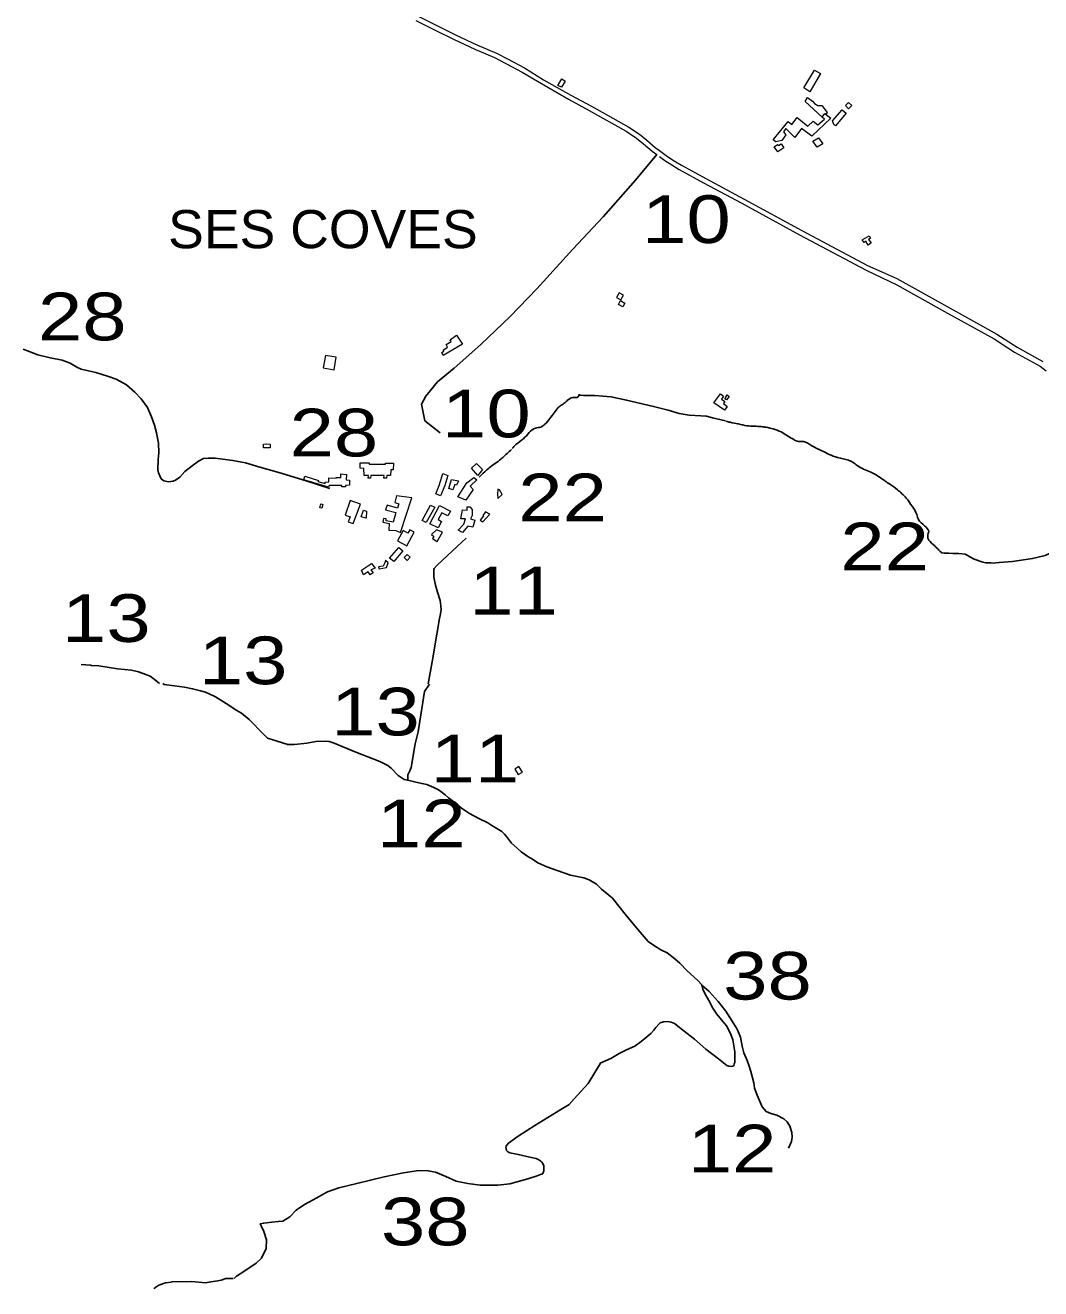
# Model space of a CAD drawing. Extents: x 476989 to 498418, y 4381813 to 4416555.
# Drawn here: x 484535 to 485599, y 4385813 to 4387137 of the extents above; entities that cross this region are included whole.
import ezdxf
from ezdxf.enums import TextEntityAlignment as Align

# ---------------------------------------------------------------- set-up
doc = ezdxf.new("R2010")
doc.units = 0
doc.header["$LTSCALE"] = 20
doc.linetypes.add('MEDIUM_DASHED', pattern=[4.5, 3, -1.5])
for name, color, linetype, lineweight in [('13', 7, 'Continuous', 13), ('36', 7, 'Continuous', 13), ('47', 7, 'Continuous', 13), ('48', 7, 'MEDIUM_DASHED', 13), ('6', 7, 'Continuous', 25)]:
    doc.layers.add(name, color=color, linetype=linetype, lineweight=lineweight)
doc.layers.add('7', color=7, linetype='Continuous')

msp = doc.modelspace()

# ---------------------------------------------------------------- linework, layer by layer
at = {"layer": '36'}
for points in [[(484944.1, 4387141.99), (484964.47, 4387131.61), (484984.32, 4387121.95), (485006.12, 4387111.66), (485026.67, 4387103.08), (485038.55, 4387096.84), (485055.45, 4387087.66), (485071.49, 4387078.37), (485104.22, 4387059.29), (485125.9, 4387047.57), (485164.72, 4387025.8), (485175.49, 4387018.62), (485182.86, 4387012.44), (485191.84, 4387004.83), (485196.68, 4387001.41)], [(484946.46, 4387146.48), (484966.73, 4387136.15), (484986.51, 4387126.53), (485008.19, 4387116.3), (485028.83, 4387107.68), (485040.94, 4387101.32), (485057.93, 4387092.09), (485077.85, 4387079.8), (485106.7, 4387063.72), (485128.35, 4387052.02), (485167.37, 4387030.13), (485178.54, 4387022.69), (485186.13, 4387016.32), (485194.95, 4387008.84), (485199.56, 4387005.59), (485207.95, 4386999.32), (485214.97, 4386994.81), (485222.72, 4386990.21), (485248.09, 4386976.31), (485288.29, 4386954.73), (485348.62, 4386921.76), (485417.64, 4386885.14), (485448.2, 4386871.57)], [(485199.66, 4386999.18), (485205.06, 4386995.15), (485212.3, 4386990.49), (485220.21, 4386985.8), (485245.67, 4386971.85), (485285.88, 4386950.27), (485346.2, 4386917.3), (485416.17, 4386880.07), (485448.2, 4386864.89)], [(485448.2, 4386871.57), (485504.34, 4386840.28), (485553.22, 4386813.06), (485574.47, 4386799.34), (485601.49, 4386784.39)], [(485448.2, 4386864.89), (485501.51, 4386835.18), (485550.21, 4386808.06), (485564.49, 4386798.84)], [(485564.49, 4386798.84), (485571.47, 4386794.33), (485598.37, 4386779.45), (485604.95, 4386774.75)]]:
    msp.add_lwpolyline(points, dxfattribs=at)
at = {"layer": '47'}
for points in [[(485368.22, 4387086.2), (485357.27, 4387067.19), (485350.67, 4387071.13), (485362.11, 4387089.78)], [(485097.24, 4387080.64), (485100.57, 4387078.42), (485096.97, 4387071.84), (485093.08, 4387073.8)], [(485394.39, 4387052.63), (485397.68, 4387049.39), (485401.01, 4387052.87), (485397.7, 4387056.05)], [(485372.99, 4387044.3), (485379, 4387039.44), (485359.12, 4387020.48), (485348.48, 4387028.62), (485341.4, 4387019.09), (485332.09, 4387028.81), (485329.57, 4387025.05), (485331.9, 4387022.2), (485327.68, 4387016.19), (485321.58, 4387014.58), (485318.65, 4387016.84), (485334.49, 4387035.93), (485338.08, 4387032.94), (485343.81, 4387040.06), (485355.18, 4387030.96), (485360.7, 4387036.3), (485365.34, 4387032.5), (485372.61, 4387038.49), (485370.16, 4387040.56)], [(485391.11, 4387048.23), (485395.02, 4387044.71), (485384.02, 4387031.63), (485382.12, 4387032.82), (485380.94, 4387036.71)], [(485327, 4387012.45), (485329.8, 4387008.42), (485323.53, 4387004.21), (485319.77, 4387009.59), (485323.16, 4387012.07), (485324.25, 4387010.89)], [(485366.04, 4387018.89), (485370.57, 4387012.53), (485364.64, 4387009.06), (485360.3, 4387015.36)], [(485414.1, 4386909.21), (485412, 4386912.03), (485419.3, 4386916.24), (485420.78, 4386913.81), (485418.73, 4386912.47), (485421.25, 4386908.69), (485418.22, 4386906.38), (485415.81, 4386910.6)], [(485159.11, 4386849.19), (485161.77, 4386854.02), (485157.33, 4386856.45), (485154.56, 4386851.45)], [(485158.77, 4386848.3), (485163.02, 4386845.74), (485161.19, 4386841.81), (485156.57, 4386844.26)], [(484986.77, 4386812.07), (484993.03, 4386802.65), (484972.62, 4386790.82), (484971.23, 4386794), (484973.4, 4386795.11), (484972.72, 4386796.45), (484977.43, 4386799.32), (484975.89, 4386802.33), (484981.16, 4386805.24), (484980.03, 4386807.2)], [(484849.44, 4386790.77), (484846.94, 4386777.85), (484858.51, 4386775.82), (484860.5, 4386788.91)], [(485267.8, 4386733.43), (485256.48, 4386741.12), (485263.36, 4386750.59), (485266.67, 4386747.96), (485264.52, 4386745.08), (485268.18, 4386742.35), (485266.49, 4386740.36), (485270.62, 4386737.25)], [(485272.72, 4386747.91), (485269.84, 4386744.21), (485268.02, 4386745.4), (485269.25, 4386747.04), (485268.91, 4386747.33), (485270.37, 4386749.54)], [(484791.59, 4386697.69), (484791.41, 4386693.78), (484784.36, 4386694.03), (484784.57, 4386697.72), (484787.22, 4386698.3)], [(484912.38, 4386677.94), (484920.75, 4386677.78), (484920.46, 4386671.05), (484917.81, 4386671.05), (484917.39, 4386664.88), (484913.7, 4386664.88), (484913.51, 4386662.27), (484910.67, 4386662.23), (484910.82, 4386664.83), (484896.88, 4386664.88), (484896.69, 4386662.27), (484894.26, 4386662.29), (484894.38, 4386664.94), (484889.81, 4386664.95), (484889.46, 4386672.4), (484885.79, 4386672.68), (484885.72, 4386678.1), (484888.41, 4386678.06), (484895.26, 4386678.11), (484895.2, 4386676.96), (484912.45, 4386676.68)], [(484874.65, 4386654.69), (484870.48, 4386654.58), (484870.46, 4386653.02), (484866.58, 4386653.01), (484866.49, 4386654.59), (484853.21, 4386654.39), (484852.68, 4386652.83), (484826.61, 4386660.29), (484827.71, 4386664.28), (484842.06, 4386659.71), (484841.42, 4386658.6), (484849.07, 4386656.47), (484849.11, 4386658.07), (484852.95, 4386658.16), (484852.97, 4386662.54), (484860.65, 4386662.23), (484860.59, 4386662.87), (484865.39, 4386662.92), (484865.39, 4386666.55), (484871.56, 4386665.85), (484871.09, 4386660.58), (484874.62, 4386659.92)], [(484965.07, 4386645.88), (484968.64, 4386654.55), (484972.34, 4386666.93), (484977.49, 4386665.02), (484974.53, 4386654.43), (484969.91, 4386643.72)], [(485009.06, 4386664.93), (485002.56, 4386672.56), (485007.64, 4386677.52), (485014.09, 4386671.17)], [(484982.82, 4386649.95), (484978.55, 4386651.27), (484981.38, 4386660.9), (484988.94, 4386659.2), (484986.79, 4386654.97), (484985.12, 4386655.57)], [(484996.43, 4386639.1), (484988.3, 4386642.47), (484997.48, 4386657.34), (485004.88, 4386662.98), (485007.91, 4386660.32), (485001.03, 4386653.8), (485004.26, 4386650.11)], [(484878.58, 4386614.5), (484885.94, 4386635.06), (484875.22, 4386638.61), (484870.18, 4386623.37), (484875.16, 4386621.77), (484873.26, 4386616.47)], [(484928.18, 4386605.08), (484939.97, 4386641.51), (484923.72, 4386643.6), (484923.72, 4386643.6), (484922.15, 4386636.75), (484926.42, 4386635.39), (484924.89, 4386630.56), (484914.1, 4386633.92), (484912.38, 4386628.99), (484923.2, 4386626.01), (484920.36, 4386615.87), (484913.03, 4386617.33), (484913.16, 4386619.43), (484910.06, 4386619.81), (484909.64, 4386615.9), (484916.17, 4386614.67), (484915.69, 4386607.82), (484923.12, 4386607.18)], [(485030.11, 4386650.61), (485029.58, 4386644.86), (485029.99, 4386640.89), (485034.75, 4386645), (485031.79, 4386649.97)], [(484844.5, 4386635.18), (484846.55, 4386634.63), (484845.65, 4386630.54), (484843.47, 4386631)], [(484886.83, 4386621.49), (484889.37, 4386628.45), (484892.44, 4386627.58), (484892, 4386620.32)], [(484963.89, 4386631.61), (484955.07, 4386615.72), (484950.82, 4386617.68), (484959.38, 4386633.93)], [(484967.69, 4386609.95), (484958.91, 4386614.38), (484968.97, 4386633.65), (484980.35, 4386627.47), (484977.58, 4386622.58), (484971.41, 4386625.97), (484967.47, 4386618.74), (484971.14, 4386616.66)], [(484988.42, 4386607.8), (484994.31, 4386613.95), (484996.03, 4386619.44), (484991.42, 4386619.37), (484993.16, 4386629.13), (484997.81, 4386628.54), (484998.06, 4386632.15), (485000.73, 4386632.13), (485003.26, 4386629.33), (485003.18, 4386623.16), (485001.26, 4386619.51), (485005.92, 4386618.3), (485003.83, 4386610.74), (484998.71, 4386611.89), (484992.95, 4386605.26)], [(485011.45, 4386618.18), (485014.46, 4386616.41), (485021.54, 4386624.32), (485017.31, 4386627), (485014.34, 4386623.18), (485015.15, 4386622.6)], [(484930.93, 4386607.22), (484924.86, 4386596.58), (484934.84, 4386591.38), (484942.38, 4386605.69), (484937.68, 4386607.95), (484935.78, 4386604.53)], [(484966.64, 4386595.92), (484972.22, 4386605.45), (484965.86, 4386607.86), (484960.42, 4386603.19), (484963.09, 4386601.11), (484961.54, 4386598.91)], [(484930.53, 4386586.08), (484920.88, 4386574.84), (484916.58, 4386578.14), (484926.15, 4386589.6)], [(484897.59, 4386572.87), (484901.46, 4386567.77), (484897.1, 4386566.06), (484899.31, 4386562.89), (484896.16, 4386560.94), (484894.13, 4386564.12), (484889.43, 4386560.81), (484887.27, 4386565.75)], [(484911.46, 4386573.35), (484909.91, 4386569.85), (484905.06, 4386569.06), (484905.54, 4386567.13), (484913.36, 4386568.57), (484915.04, 4386573.28), (484912.15, 4386575.78)], [(484931.93, 4386579.1), (484935.2, 4386575.97), (484938.33, 4386579.24), (484934.89, 4386582.26)]]:
    msp.add_lwpolyline(points, close=True, dxfattribs=at)
msp.add_lwpolyline([(485370.16, 4387040.56), (485352.1, 4387056.87), (485354.61, 4387061.18), (485359.78, 4387057.35), (485362.15, 4387054.85), (485365.59, 4387052.79), (485369.74, 4387052.73), (485375.25, 4387045.3), (485374.01, 4387043.48)], dxfattribs=at)
at = {"layer": '48'}
msp.add_lwpolyline([(485047.97, 4386357.07), (485051.39, 4386351.42), (485055.76, 4386354.03), (485052.03, 4386360.03)], close=True, dxfattribs=at)
at = {"layer": '6'}
msp.add_line((484669.78, 4386451.55), (484675.59, 4386447), dxfattribs=at)
for points in [[(485196.68, 4387001.41), (485174.53, 4386974.43), (485140.42, 4386936.16), (485108.67, 4386902.09), (485070.95, 4386860.47), (485042.96, 4386831.45), (485012.41, 4386802.17), (484984.19, 4386777.31), (484966.85, 4386762.96), (484954.68, 4386748.08), (484950.17, 4386739.57), (484953.68, 4386722.28), (484969.49, 4386709.51)], [(484532.44, 4386797.25), (484547.84, 4386791.37), (484560.89, 4386788.41), (484573.56, 4386785.73), (484581.82, 4386782.58), (484588.73, 4386778.34), (484593.26, 4386776.54), (484608.53, 4386772.83), (484621.89, 4386768.75), (484629.95, 4386765.83), (484640.85, 4386759.96), (484649.61, 4386752.18), (484656.1, 4386745.44), (484662.74, 4386736.14), (484667.21, 4386726.6), (484670.12, 4386717.75), (484672.45, 4386709.7), (484674.51, 4386698.8), (484674.86, 4386688.69), (484673.94, 4386681.56), (484673.61, 4386671.01), (484674.2, 4386667.61), (484677.03, 4386661.52), (484680.13, 4386659.31), (484684.79, 4386658.31)], [(485115.8, 4386749.57), (485116.23, 4386749.1), (485119.88, 4386748.84), (485125.2, 4386748.79), (485131.48, 4386748.94), (485148.96, 4386747.36), (485165.08, 4386743.99), (485193.34, 4386737.28), (485208.6, 4386733.52), (485219.97, 4386729.79), (485230.45, 4386728.1), (485243, 4386727.43), (485248.7, 4386726.99), (485255.02, 4386725.5), (485268.69, 4386722.23)], [(484853.83, 4386651.43), (484829.07, 4386659.2), (484800.41, 4386667.98), (484780.66, 4386673.63), (484765.62, 4386678.12), (484752.26, 4386680.6), (484739.16, 4386682.53), (484733.6, 4386683.05), (484726.44, 4386683.19), (484721.56, 4386682.61), (484716.47, 4386680.06), (484709.49, 4386675.03), (484701.94, 4386668.98), (484696.71, 4386663.28), (484692.09, 4386660), (484689.62, 4386659.03), (484684.79, 4386658.31)], [(484996.82, 4386599.17), (484987.66, 4386591.04), (484966.55, 4386571), (484963.37, 4386567.3), (484963.02, 4386566.37), (484962.82, 4386558.23), (484964.9, 4386549.85), (484966.92, 4386542.55), (484969.46, 4386533.86), (484970.42, 4386528.49), (484970.53, 4386524.01), (484969.46, 4386518.29), (484968.88, 4386515.18), (484965.99, 4386498.52), (484961.18, 4386469.77), (484956.92, 4386446.46)], [(485614.42, 4386588.88), (485608.24, 4386583.25), (485603.79, 4386581.02), (485590.67, 4386577.99), (485569.57, 4386574.82), (485555.53, 4386573.67), (485552.14, 4386573.42), (485549.36, 4386573.22), (485546.88, 4386573.26), (485541.5, 4386573.42), (485538.28, 4386574.27), (485529.3, 4386577.31), (485524.93, 4386579.57), (485522.13, 4386581.47), (485519.82, 4386582.6), (485513.12, 4386583.13), (485507.1, 4386583.36), (485502.68, 4386583.42), (485498.06, 4386583.56), (485495.44, 4386583.92), (485492.88, 4386586.05)], [(484593.43, 4386466.83), (484593.45, 4386466.82), (484603.22, 4386466), (484604.19, 4386465.78), (484612, 4386465.4), (484631.54, 4386462.29), (484646.09, 4386460.77), (484653.53, 4386459.28), (484658.44, 4386457.47), (484658.41, 4386457.42), (484665.79, 4386454.57), (484669.78, 4386451.55)], [(484678.9, 4386446.99), (484680.33, 4386445.85), (484691.09, 4386444.37), (484701.51, 4386443.23), (484710.08, 4386441.49), (484718.53, 4386439.37), (484723.57, 4386437.83), (484728.11, 4386435.66), (484734.03, 4386433), (484745.31, 4386426.03), (484756.55, 4386418.6), (484761.33, 4386415.93), (484769.5, 4386409.28), (484784.5, 4386393.85), (484788.56, 4386389.73), (484793.23, 4386388.09), (484809.87, 4386382.9)], [(484958.3, 4386446.26), (484953.04, 4386438.59), (484946.62, 4386396.38), (484943.54, 4386383.67), (484939.22, 4386358.89), (484937.9, 4386355.26), (484935.85, 4386351.35), (484935.78, 4386345.49)], [(484809.2, 4386382.93), (484816.87, 4386383.07), (484829.76, 4386384.43), (484839.45, 4386386.17), (484849.35, 4386386.59), (484853.26, 4386386.23), (484858.54, 4386384.32), (484881.13, 4386374.95), (484906.55, 4386365.25), (484914.67, 4386360.86), (484918.39, 4386358.2), (484925.44, 4386350.65), (484931.98, 4386346.41), (484938.51, 4386345.07), (484942.87, 4386343.84)], [(484942.87, 4386343.84), (484950.32, 4386342.24), (484955.52, 4386340.89), (484963.01, 4386337.82), (484967.78, 4386335.39), (484970.48, 4386333.62), (484974.91, 4386330.09), (484978.3, 4386327.13), (484983.78, 4386322.85), (484991.83, 4386316.23), (485000.22, 4386310.65), (485010.22, 4386305.49), (485019.61, 4386300.9), (485023.89, 4386297.97), (485034.3, 4386291.84), (485037.17, 4386288.93), (485039.13, 4386286.4), (485044.46, 4386279.63), (485050.26, 4386274.45), (485054.6, 4386270.52), (485061.48, 4386265.69), (485066.31, 4386262.9), (485072.11, 4386258.98), (485081.56, 4386254.75), (485092.29, 4386251), (485106.38, 4386246.15), (485120.38, 4386243.3), (485125.75, 4386241.04), (485133.62, 4386236.48), (485138.8, 4386231.28), (485150.15, 4386221.79), (485163.42, 4386205.22), (485177.27, 4386188.83), (485187.8, 4386176.49), (485194.39, 4386172.03), (485200.95, 4386167.78), (485207.56, 4386164.49), (485215.71, 4386158.18), (485220.87, 4386153.67), (485228.5, 4386145.73), (485239.66, 4386135.6), (485243.92, 4386131.21)], [(485137.42, 4386048.97), (485148.63, 4386053.82), (485157.15, 4386059.18), (485164.93, 4386062.86), (485173.69, 4386066.86), (485180.28, 4386071.55), (485186.41, 4386076.63), (485190.45, 4386080.03), (485193.63, 4386083.43), (485195.76, 4386086.35), (485199.08, 4386090.25), (485200.34, 4386091.24), (485203.86, 4386092.43), (485208.21, 4386092.7), (485211.9, 4386092.03), (485215.19, 4386090.42), (485225.5, 4386082.35), (485236.31, 4386074.25), (485247.96, 4386063.67), (485261.46, 4386053.34), (485269.97, 4386046.64), (485272.18, 4386045.77), (485274.75, 4386045.53), (485276.27, 4386045.91), (485277.39, 4386046.58), (485277.29, 4386046.46), (485277.27, 4386046.28), (485277.91, 4386048.23), (485278.42, 4386049.78), (485278.61, 4386055.69), (485278.62, 4386060.86), (485277.55, 4386067.01), (485276.23, 4386073.52), (485274, 4386079.95), (485269.68, 4386088.07), (485264.45, 4386094.26), (485259.77, 4386100.29), (485255.39, 4386106.74), (485251.08, 4386114.81), (485247.23, 4386121.17), (485244.96, 4386126.54), (485243.92, 4386131.21)], [(485244.01, 4386130.88), (485251.73, 4386124.05), (485261.17, 4386113.52), (485269.16, 4386103.38), (485277.47, 4386090.36), (485281.02, 4386084.45), (485284.58, 4386076.08), (485286.34, 4386066.85), (485288.02, 4386059.68), (485291.51, 4386051.58), (485293.26, 4386046.93), (485295.26, 4386040.29), (485298.32, 4386028.5), (485299.16, 4386022.88), (485301.83, 4386015.45), (485307.25, 4386003.05), (485311.27, 4385998.43), (485316.17, 4385996.13), (485322.45, 4385994.43), (485329.69, 4385990.5), (485333.27, 4385987.49), (485336.16, 4385982.91), (485338.39, 4385976.12), (485338.64, 4385971.4), (485337.85, 4385966.8), (485334.87, 4385960.03)], [(484753.57, 4385823.35), (484756.07, 4385825.8), (484763.83, 4385830.53), (484776.58, 4385839.37), (484782.34, 4385844.43), (484787.2, 4385854.84), (484787.51, 4385863.86), (484784.87, 4385872.53), (484782.19, 4385877.63), (484780.99, 4385880.64), (484784.76, 4385881.31), (484793.02, 4385882.42), (484799.69, 4385882.89), (484804.87, 4385883.25), (484812.21, 4385887.91), (484818.61, 4385894.93), (484827.29, 4385900.91), (484836.49, 4385905.57), (484851.49, 4385914.04), (484863.4, 4385918.36), (484882.15, 4385922.96), (484896.7, 4385926.47), (484910.78, 4385929.65), (484931.26, 4385933.88), (484944.85, 4385936.14), (484954.98, 4385936.35), (484964.69, 4385934.66), (484975.5, 4385930.27), (484986.54, 4385925.21), (484998.58, 4385922.91), (485011.63, 4385921.23), (485030.11, 4385921.12), (485042.66, 4385922.44), (485061.41, 4385927.72), (485071.46, 4385930.94), (485074.81, 4385932.11), (485076.32, 4385932.73), (485076.79, 4385932.96), (485077.28, 4385933.45), (485078.11, 4385936.24), (485078.35, 4385938.73), (485078.24, 4385941.42), (485077.1, 4385943.96), (485076.09, 4385945.28), (485075.2, 4385946.11), (485073.05, 4385947.62), (485070.18, 4385948.95), (485061.85, 4385950.92), (485052.97, 4385952.73), (485042.57, 4385954.94), (485040.72, 4385956.12), (485039.31, 4385957.48), (485038.69, 4385959.31), (485038.59, 4385960.67), (485038.85, 4385961.89), (485039.56, 4385963.1), (485041.35, 4385965.05), (485051.42, 4385972.39), (485069, 4385983.72), (485096.24, 4386000.56), (485104.76, 4386005.49), (485110.15, 4386011.63), (485124.59, 4386027.56), (485137.59, 4386048.93)], [(484669.76, 4385812.52), (484670.46, 4385813.3), (484674.66, 4385816.15), (484681.59, 4385818.87), (484687.68, 4385819.41), (484687.98, 4385819.58), (484709.29, 4385820.21), (484723.73, 4385818.84), (484729.17, 4385819.65), (484736.43, 4385820.77), (484740.02, 4385821.59), (484744.86, 4385823.22), (484752.62, 4385823.08)]]:
    msp.add_lwpolyline(points, dxfattribs=at)
for points in [[(485115.36, 4386750.06), (485114.19, 4386747.52), (485113.18, 4386746.88), (485109.53, 4386746.71), (485104.69, 4386745.06), (485100.59, 4386741.44), (485096.18, 4386738.34), (485093.43, 4386736.08), (485088.97, 4386730.52), (485084.71, 4386724.86), (485079.08, 4386718.3), (485075.29, 4386715.77), (485069.5, 4386714.61), (485062.95, 4386709.95), (485056.92, 4386703.52), (485049.07, 4386697.32), (485044.98, 4386693.19)], [(485269.25, 4386721.86), (485273.58, 4386720.69), (485281.99, 4386718.99), (485291.13, 4386717.08), (485298.97, 4386716.54), (485306.16, 4386716.18), (485311.27, 4386715.46), (485318.78, 4386713.76), (485326.94, 4386710.61), (485333.63, 4386706.4), (485340.32, 4386702.69), (485343.71, 4386700.79), (485350.33, 4386700.57), (485359.32, 4386695.9), (485369.58, 4386690.94), (485377.37, 4386687.13), (485386.17, 4386683.79), (485392.17, 4386682.32), (485402.4, 4386678.62), (485406.74, 4386675.4), (485420.48, 4386668.69), (485428.53, 4386664.29), (485438.68, 4386657.3), (485441.05, 4386655.72), (485448.83, 4386650.03), (485458.08, 4386641.35), (485464.26, 4386632.88), (485469.2, 4386623.92), (485470.98, 4386618.97), (485477.37, 4386612.21), (485481.67, 4386606.48), (485480.65, 4386601.56), (485480.95, 4386599.19), (485486.47, 4386592.56), (485492.66, 4386586.48)], [(485044.48, 4386692.16), (485035.19, 4386683.87), (485033.34, 4386682.1), (485020.94, 4386672.97), (485016.38, 4386668.89), (485010.36, 4386663.05)]]:
    msp.add_spline(points, degree=3, dxfattribs=at)

# ---------------------------------------------------------------- texts
at = {"layer": '13', "width": 1.25}
for s, p in [('10', (485227.72, 4386908.63)), ('28', (484594.48, 4386806.61)), ('10', (485018.06, 4386704.9)), ('28', (484858.22, 4386684.95)), ('22', (485097.88, 4386616.91)), ('22', (485435.5, 4386565.58)), ('11', (485046.7, 4386519.24)), ('13', (484619.71, 4386490.5)), ('13', (484763.07, 4386446.16)), ('13', (484901.82, 4386392.49)), ('11', (485006.11, 4386343.25)), ('12', (484949.89, 4386275.21)), ('38', (485312.74, 4386115.62)), ('12', (485275.65, 4385934.42)), ('38', (484954.01, 4385858.01))]:
    msp.add_text(s, height=50, dxfattribs=at).set_placement(p, align=Align.CENTER)
at = {"layer": '7', "width": 1.05}
msp.add_text('SES COVES', height=40, dxfattribs=at).set_placement((484846.71, 4386903.18), align=Align.CENTER)

doc.saveas('drawing.dxf')
